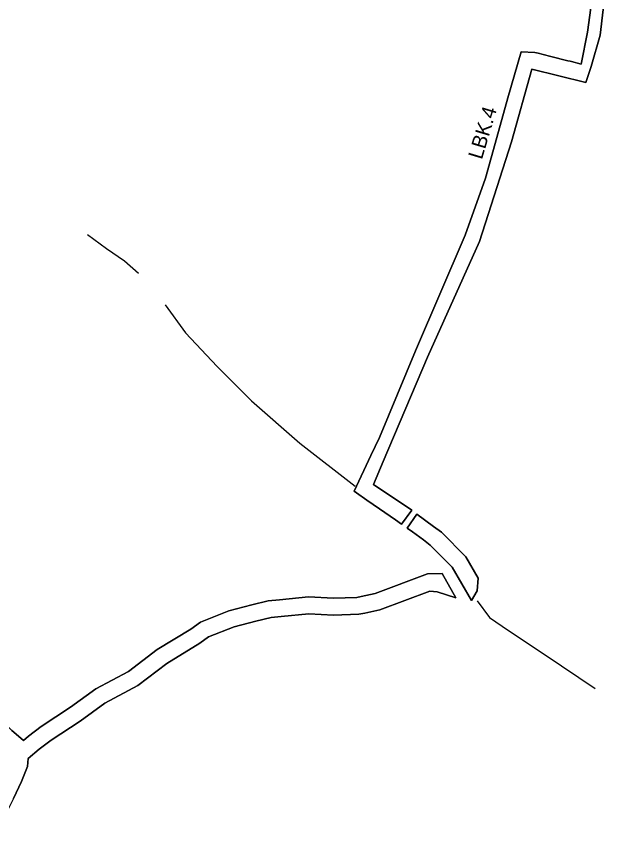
# Model space of a CAD drawing. Extents: x -555426 to -553015, y -1186745 to -1182595.
# Drawn here: x -553542 to -553015, y -1186231 to -1185506 of the extents above; entities that cross this region are included whole.
import ezdxf

# ---------------------------------------------------------------- set-up
doc = ezdxf.new("R2010")
doc.units = 0
for name, color, linetype in [('Level 12', 7, 'Continuous'), ('Level 51', 7, 'Continuous'), ('USES_ID', 7, 'Continuous'), ('USES_LBK_navrh', 7, 'Continuous'), ('USES_LBK_stav', 7, 'Continuous')]:
    doc.layers.add(name, color=color, linetype=linetype)

msp = doc.modelspace()

# ---------------------------------------------------------------- linework, layer by layer
at = {"layer": 'Level 12'}
for points in [[(-553034.93, -1185564.73), (-553030.13, -1185550.39), (-553022.24, -1185522.46), (-553016.78, -1185476.64), (-553015.45, -1185443.7), (-553020.83, -1185394.62), (-553028.51, -1185379.69), (-553056.68, -1185336.83), (-553059.75, -1185331.58), (-553062.27, -1185327.43), (-553065.55, -1185322), (-553070.46, -1185313.92), (-553074.85, -1185306.8), (-553080.44, -1185299.18), (-553082.87, -1185302.3)], [(-553027.49, -1185476.25), (-553033.31, -1185519.72), (-553038.96, -1185548.27), (-553047.67, -1185546.08), (-553048.91, -1185545.77), (-553050.91, -1185545.27), (-553053.3, -1185544.68), (-553063.75, -1185542.07), (-553066.22, -1185541.44), (-553072.87, -1185539.73), (-553077.5, -1185538.57), (-553079.01, -1185538.14), (-553080.42, -1185537.9), (-553092.39, -1185537.23), (-553104.36, -1185578.25), (-553114.18, -1185613.7), (-553124.36, -1185649.89), (-553142.42, -1185700.66), (-553186.75, -1185803.57), (-553218.6, -1185880.58), (-553226.41, -1185896.66), (-553241.32, -1185928.48), (-553239.31, -1185930.03), (-553229.98, -1185936.55), (-553218.58, -1185944.24), (-553204.56, -1185953.8), (-553198.95, -1185957.78)], [(-553198.95, -1185957.78), (-553190.04, -1185945.32), (-553224.04, -1185922.54), (-553215.31, -1185901.96), (-553175.94, -1185809.23), (-553129.62, -1185706.16), (-553101.04, -1185617.53), (-553083.08, -1185552.82), (-553034.93, -1185564.73)], [(-553136.76, -1186025.81), (-553131.64, -1186017.15), (-553130.88, -1186005.96), (-553141.82, -1185986.94), (-553163.58, -1185965.02), (-553170.65, -1185959.74), (-553185.4, -1185948.91), (-553193.99, -1185961.2)], [(-553193.99, -1185961.2), (-553189.33, -1185964.5), (-553179.63, -1185971.75), (-553173.45, -1185976.37), (-553153.84, -1185996.12), (-553136.76, -1186025.81)], [(-553150.76, -1186023.24), (-553162.91, -1186001.77), (-553175.83, -1186001.96), (-553222.52, -1186019.49), (-553235.04, -1186022.23), (-553238.87, -1186023.05), (-553259.58, -1186023.74), (-553282.02, -1186022.43), (-553307.71, -1186025.17), (-553317.74, -1186025.99), (-553332.41, -1186029.69), (-553352.72, -1186034.99), (-553378.05, -1186044.88), (-553386.83, -1186051.11), (-553416.57, -1186069.41), (-553442.07, -1186088.79), (-553471.26, -1186104.37), (-553493.84, -1186120.69), (-553519.85, -1186137.77), (-553531.2, -1186146.37), (-553535.86, -1186150.36), (-553538.1, -1186148.41), (-553546.02, -1186141.35)], [(-553544.71, -1186202.05), (-553537.64, -1186186.86), (-553532.26, -1186173.57), (-553531.6, -1186166.45), (-553521.79, -1186158.06), (-553511.19, -1186150.03), (-553485.32, -1186133.04), (-553463.3, -1186117.12), (-553433.95, -1186101.46), (-553408.08, -1186081.8), (-553378.55, -1186063.63), (-553370.87, -1186058.18), (-553348.08, -1186049.28), (-553328.68, -1186044.22), (-553315.27, -1186040.84), (-553306.3, -1186040.1), (-553281.66, -1186037.48), (-553259.77, -1186038.75), (-553237.04, -1186038), (-553231.86, -1186036.89), (-553218.26, -1186033.91), (-553173.99, -1186017.29), (-553167.22, -1186018.11), (-553150.76, -1186023.24)]]:
    msp.add_lwpolyline(points, dxfattribs=at)
at = {"layer": 'Level 51'}
for points in [[(-553478.79, -1185700.06), (-553461.7, -1185712.42), (-553445.65, -1185723.51), (-553433.4, -1185734.25)], [(-553409.61, -1185762.55), (-553391.36, -1185787.61), (-553363.18, -1185817.41), (-553332.8, -1185848.02), (-553289.6, -1185885.56), (-553240.23, -1185923.95)], [(-553131.63, -1186026.06), (-553120.81, -1186040.88), (-553103.95, -1186052.43), (-553071.26, -1186074.03), (-553026.68, -1186104.06)]]:
    msp.add_lwpolyline(points, dxfattribs=at)
at = {"layer": 'USES_LBK_navrh'}
for p, q in [((-553189.33, -1185964.5), (-553193.99, -1185961.2)), ((-553179.63, -1185971.75), (-553189.33, -1185964.5)), ((-553163.58, -1185965.02), (-553141.82, -1185986.94)), ((-553141.82, -1185986.94), (-553130.88, -1186005.96)), ((-553136.76, -1186025.81), (-553153.84, -1185996.12)), ((-553162.91, -1186001.77), (-553150.76, -1186023.24)), ((-553237.04, -1186038), (-553259.77, -1186038.75)), ((-553386.83, -1186051.11), (-553378.05, -1186044.88)), ((-553328.68, -1186044.22), (-553348.08, -1186049.28)), ((-553416.57, -1186069.41), (-553386.83, -1186051.11)), ((-553442.07, -1186088.79), (-553416.57, -1186069.41)), ((-553471.26, -1186104.37), (-553442.07, -1186088.79))]:
    msp.add_line(p, q, dxfattribs=at)
for points in [[(-553193.99, -1185961.2), (-553185.4, -1185948.91), (-553170.65, -1185959.74), (-553163.58, -1185965.02)], [(-553153.84, -1185996.12), (-553173.45, -1185976.37), (-553179.63, -1185971.75)], [(-553238.87, -1186023.05), (-553235.04, -1186022.23), (-553222.52, -1186019.49), (-553175.83, -1186001.96), (-553162.91, -1186001.77)], [(-553130.88, -1186005.96), (-553131.64, -1186017.15), (-553136.76, -1186025.81)], [(-553150.76, -1186023.24), (-553167.22, -1186018.11), (-553173.99, -1186017.29), (-553218.26, -1186033.91)], [(-553378.05, -1186044.88), (-553352.72, -1186034.99), (-553332.41, -1186029.69), (-553317.74, -1186025.99), (-553307.71, -1186025.17)], [(-553307.71, -1186025.17), (-553282.02, -1186022.43), (-553259.58, -1186023.74), (-553238.87, -1186023.05)], [(-553218.26, -1186033.91), (-553231.86, -1186036.89), (-553237.04, -1186038)], [(-553259.77, -1186038.75), (-553281.66, -1186037.48), (-553306.3, -1186040.1), (-553315.27, -1186040.84), (-553328.68, -1186044.22)], [(-553348.08, -1186049.28), (-553370.87, -1186058.18), (-553378.55, -1186063.63), (-553408.08, -1186081.8)], [(-553408.08, -1186081.8), (-553433.95, -1186101.46), (-553463.3, -1186117.12), (-553485.32, -1186133.04), (-553511.19, -1186150.03), (-553521.79, -1186158.06), (-553531.6, -1186166.45), (-553532.26, -1186173.57)], [(-553531.2, -1186146.37), (-553519.85, -1186137.77), (-553493.84, -1186120.69), (-553471.26, -1186104.37)], [(-553557.15, -1186130.6), (-553553.04, -1186134.5), (-553548.68, -1186138.88), (-553546.02, -1186141.35), (-553538.1, -1186148.41)], [(-553538.1, -1186148.41), (-553535.86, -1186150.36), (-553531.2, -1186146.37)], [(-553532.26, -1186173.57), (-553537.64, -1186186.86), (-553544.71, -1186202.05), (-553551.72, -1186216.33), (-553558.79, -1186230.64)]]:
    msp.add_lwpolyline(points, dxfattribs=at)
at = {"layer": 'USES_LBK_stav'}
for points in [[(-553082.87, -1185302.3), (-553080.44, -1185299.18), (-553074.85, -1185306.8), (-553070.46, -1185313.92), (-553065.55, -1185322), (-553062.27, -1185327.43), (-553059.75, -1185331.58), (-553056.68, -1185336.83), (-553028.51, -1185379.69), (-553020.83, -1185394.62), (-553015.45, -1185443.7), (-553016.78, -1185476.64), (-553022.24, -1185522.46), (-553030.13, -1185550.39), (-553034.93, -1185564.73)], [(-553198.95, -1185957.78), (-553204.56, -1185953.8), (-553218.58, -1185944.24), (-553229.98, -1185936.55), (-553239.31, -1185930.03), (-553241.32, -1185928.48), (-553226.41, -1185896.66), (-553218.6, -1185880.58), (-553186.75, -1185803.57), (-553142.42, -1185700.66), (-553124.36, -1185649.89), (-553114.18, -1185613.7), (-553104.36, -1185578.25), (-553092.39, -1185537.23), (-553080.42, -1185537.9), (-553079.01, -1185538.14), (-553077.5, -1185538.57), (-553072.87, -1185539.73), (-553066.22, -1185541.44), (-553063.75, -1185542.07), (-553053.3, -1185544.68), (-553050.91, -1185545.27), (-553048.91, -1185545.77), (-553047.67, -1185546.08), (-553038.96, -1185548.27), (-553033.31, -1185519.72), (-553027.49, -1185476.25)], [(-553034.93, -1185564.73), (-553083.08, -1185552.82), (-553101.04, -1185617.53), (-553129.62, -1185706.16), (-553175.94, -1185809.23), (-553215.31, -1185901.96), (-553224.04, -1185922.54), (-553190.04, -1185945.32), (-553198.95, -1185957.78)]]:
    msp.add_lwpolyline(points, dxfattribs=at)

# ---------------------------------------------------------------- texts
at = {"layer": 'USES_ID'}
msp.add_text('LBK.4', height=13, rotation=73.30047, dxfattribs=at).set_placement((-553127.55, -1185633.82))

doc.saveas('drawing.dxf')
